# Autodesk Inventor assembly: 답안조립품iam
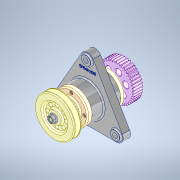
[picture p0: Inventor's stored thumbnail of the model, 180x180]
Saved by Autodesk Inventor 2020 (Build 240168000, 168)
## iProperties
Created: 2023-04
Part Number: 답안조립품iam
Document SubType Name: Assembly
Designer: home
Author: home
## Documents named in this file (11)
- C:\Users\home\Desktop\730407V1023\답안조립품iam.iam
- C:\Users\home\Desktop\730407V1023\답안도면.ipt
- C:\Users\home\Desktop\730407V1023\묻힘키 5x5x16.ipt
- C:\Users\home\Desktop\730407V1023\베어링 6204.ipt
- C:\Users\home\Desktop\730407V1023\오일 실 20 32 8.ipt
- C:\Users\home\Desktop\730407V1023\커버.ipt
- C:\Users\home\Desktop\730407V1023\축.ipt
- C:\Users\home\Desktop\730407V1023\스퍼기어.ipt
- C:\Users\home\Desktop\730407V1023\볼트 M4 x 12.ipt
- C:\Users\home\Desktop\730407V1023\6각 플랜지 너트 M10.ipt
- C:\Users\home\Desktop\730407V1023\v-벨트풀리.ipt
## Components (3 placed, 2 different names)
1. 6각 플랜지 너트 M10:1 — Mate:25, Mate:26
2. 6각 플랜지 너트 M10:2 — Mate:34, Mate:35
3. v-벨트풀리:1 — Mate:21, Mate:22, Mate:23, Mate:24, Mate:26
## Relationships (8: Mate 8)
- Mate:21: v-벨트풀리:1
- Mate:22: v-벨트풀리:1
- Mate:23: v-벨트풀리:1
- Mate:24: v-벨트풀리:1
- Mate:25: 6각 플랜지 너트 M10:1
- Mate:26: 6각 플랜지 너트 M10:1 ↔ v-벨트풀리:1
- Mate:34: 6각 플랜지 너트 M10:2
- Mate:35: 6각 플랜지 너트 M10:2
